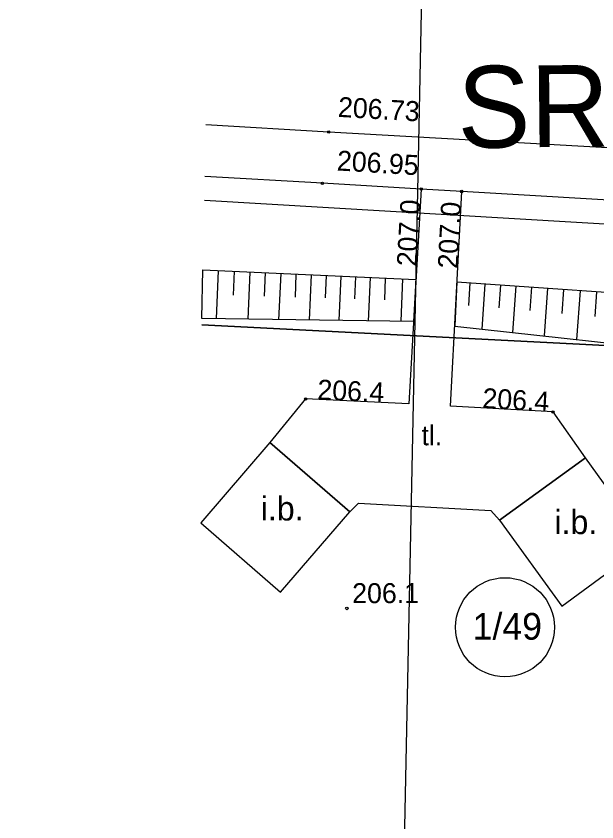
# Model space of a CAD drawing. Extents: x 6512606 to 6513006, y 6022524 to 6022728.
# Drawn here: x 6512694.69 to 6512716.48, y 6022610.86 to 6022641.08 of the extents above; entities that cross this region are included whole.
import ezdxf

# ---------------------------------------------------------------- set-up
doc = ezdxf.new("R2010")
doc.units = 0
for name, color, linetype in [('000 Inne (niezydentyfikowane)', 7, 'Continuous'), ('211-numer działki ewidencyjnej', 7, 'Continuous'), ('217-kontur klasyfikacyjny', 7, 'Continuous'), ('218-kontur użytku gruntowego', 7, 'Continuous'), ('4', 7, 'Continuous'), ('6', 7, 'Continuous'), ('chodnik (powierzchnia)', 7, 'Continuous'), ('Default', 7, 'Continuous'), ('inna budowla (powierzchnia)', 7, 'Continuous'), ('inna budowla (powierzchnia)-Atr17', 7, 'Continuous'), ('krawężnik (linia)', 7, 'Continuous'), ('maxp_inst_wodociągowa', 7, 'Continuous'), ('Obszar opracowania', 7, 'Continuous'), ('plac (powierzchnia)', 7, 'Continuous'), ('plac (powierzchnia)-Atr17', 7, 'Continuous'), ('przewód elektroenergetyczny (linia)', 7, 'Continuous'), ('punkt wysokościowy naturalny', 7, 'Continuous'), ('punkt wysokościowy naturalny-Atr2', 7, 'Continuous'), ('punkt wysokościowy sztuczny', 7, 'Continuous'), ('punkt wysokościowy sztuczny-Atr2', 7, 'Continuous'), ('skarpa nieumocniona (powierzchnia)', 7, 'Continuous')]:
    doc.layers.add(name, color=color, linetype=linetype)

# ---------------------------------------------------------------- blocks, each defined once
blk = doc.blocks.new('PW01')
at = {"layer": 'Default'}
blk.add_circle((0, 0), 0.45, dxfattribs=at)
blk = doc.blocks.new('PW02')
at = {"layer": 'Default'}
blk.add_circle((0, 0), 0.45, dxfattribs=at)

msp = doc.modelspace()

# ---------------------------------------------------------------- linework, layer by layer
at = {"layer": '000 Inne (niezydentyfikowane)'}
for p, q in [((6512702.27, 6022631.54), (6512702.19, 6022629.72)), ((6512702.87, 6022631.51), (6512702.83, 6022630.61)), ((6512703.46, 6022631.48), (6512703.38, 6022629.71)), ((6512704.04, 6022631.46), (6512704, 6022630.58)), ((6512704.62, 6022631.43), (6512704.54, 6022629.69)), ((6512705.19, 6022631.4), (6512705.16, 6022630.54)), ((6512705.76, 6022631.38), (6512705.68, 6022629.67)), ((6512706.32, 6022631.35), (6512706.28, 6022630.51)), ((6512706.88, 6022631.33), (6512706.8, 6022629.66)), ((6512707.43, 6022631.3), (6512707.39, 6022630.48)), ((6512707.98, 6022631.28), (6512707.9, 6022629.64)), ((6512708.54, 6022631.25), (6512708.51, 6022630.44)), ((6512709.19, 6022631.22), (6512709.12, 6022629.63))]:
    msp.add_line(p, q, dxfattribs=at)
for points in [[(6512711.72, 6022631.07), (6512711.66, 6022630.23)], [(6512712.28, 6022631.03), (6512712.17, 6022629.34)], [(6512712.86, 6022630.99), (6512712.8, 6022630.13)], [(6512713.44, 6022630.95), (6512713.32, 6022629.21)], [(6512714.03, 6022630.91), (6512713.97, 6022630.03)], [(6512714.63, 6022630.87), (6512714.5, 6022629.08)], [(6512715.23, 6022630.82), (6512715.17, 6022629.92)], [(6512715.85, 6022630.78), (6512715.72, 6022628.95)], [(6512716.47, 6022630.74), (6512716.41, 6022629.81)]]:
    msp.add_lwpolyline(points, dxfattribs=at)
at = {"layer": '217-kontur klasyfikacyjny'}
msp.add_lwpolyline([(6512729.5, 6022628.07), (6512701.66, 6022629.496)], dxfattribs=at)
at = {"layer": '218-kontur użytku gruntowego'}
for points in [[(6512701.66, 6022629.496), (6512729.5, 6022628.07)], [(6512729.5, 6022628.07), (6512701.66, 6022629.496)]]:
    msp.add_lwpolyline(points, dxfattribs=at)
at = {"layer": '6'}
msp.add_circle((6512713.034, 6022618.154), 1.859, dxfattribs=at)
at = {"layer": 'chodnik (powierzchnia)'}
for points in [[(6512709.89, 6022634.59), (6512706.18, 6022634.81), (6512701.774, 6022635.063)], [(6512726.27, 6022633.62), (6512711.41, 6022634.5)]]:
    msp.add_lwpolyline(points, dxfattribs=at)
at = {"layer": 'inna budowla (powierzchnia)'}
for points in [[(6512707.21, 6022622.49), (6512704.21, 6022625.09), (6512701.62, 6022622.07), (6512704.61, 6022619.47)], [(6512716.05, 6022624.51), (6512712.83, 6022622.17), (6512715.17, 6022618.95), (6512718.37, 6022621.3)]]:
    msp.add_lwpolyline(points, close=True, dxfattribs=at)
at = {"layer": 'krawężnik (linia)'}
msp.add_lwpolyline([(6512702.473, 6022669.202), (6512710.9, 6022668.72), (6512710.75, 6022664.74), (6512710.88, 6022663.85), (6512711.57, 6022663.54), (6512725.79, 6022662.66), (6512724.94, 6022645.24), (6512724.45, 6022635.71), (6512706.43, 6022636.73), (6512701.814, 6022636.999)], dxfattribs=at)
at = {"layer": 'Obszar opracowania'}
msp.add_lwpolyline([(6512710.98, 6022693.84), (6512748.35, 6022694.16), (6512798.11, 6022695.25), (6512807.47, 6022695.46), (6512809.66, 6022606.87), (6512863.71, 6022622.03), (6512875.13, 6022581.36), (6512755.22, 6022535.25), (6512691.61, 6022568.03), (6512709.16, 6022605.16)], close=True, dxfattribs=at)
at = {"layer": 'plac (powierzchnia)'}
msp.add_lwpolyline([(6512704.21, 6022625.09), (6512707.21, 6022622.49), (6512707.54, 6022622.81), (6512712.5, 6022622.54), (6512712.83, 6022622.17), (6512716.05, 6022624.51), (6512714.84, 6022626.23), (6512710.99, 6022626.45), (6512711.41, 6022634.5), (6512709.89, 6022634.59), (6512709.42, 6022626.54), (6512705.55, 6022626.72)], close=True, dxfattribs=at)
at = {"layer": 'przewód elektroenergetyczny (linia)'}
msp.add_lwpolyline([(6512701.756, 6022634.173), (6512720.37, 6022633.07), (6512728.65, 6022632.8), (6512729.84, 6022646.1), (6512731.03, 6022668.44), (6512718.53, 6022669.06), (6512712.43, 6022669.64), (6512702.495, 6022670.296)], dxfattribs=at)
at = {"layer": 'skarpa nieumocniona (powierzchnia)'}
for points in [[(6512709.69, 6022631.2), (6512709.6, 6022629.62), (6512701.66, 6022629.73), (6512701.7, 6022631.56)], [(6512709.69, 6022631.2), (6512709.6, 6022629.62), (6512701.66, 6022629.73), (6512701.7, 6022631.56)], [(6512711.15, 6022629.45), (6512720.5, 6022628.42), (6512728.41, 6022629.69), (6512727.72, 6022631.22), (6512720.25, 6022630.48), (6512711.23, 6022631.1)], [(6512711.15, 6022629.45), (6512720.5, 6022628.42), (6512728.41, 6022629.69), (6512727.72, 6022631.22), (6512720.25, 6022630.48), (6512711.23, 6022631.1)]]:
    msp.add_lwpolyline(points, close=True, dxfattribs=at)

# ---------------------------------------------------------------- block references
at = {"layer": 'punkt wysokościowy naturalny', "xscale": 0.1, "yscale": 0.10000000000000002}
for p in [(6512709.89, 6022634.59), (6512711.41, 6022634.5), (6512705.55, 6022626.72), (6512714.84, 6022626.23), (6512707.1, 6022618.86)]:
    msp.add_blockref('PW01', p, dxfattribs=at)
at = {"layer": 'punkt wysokościowy sztuczny', "xscale": 0.1, "yscale": 0.10000000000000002}
for p in [(6512706.42, 6022636.73), (6512706.18, 6022634.81)]:
    msp.add_blockref('PW02', p, dxfattribs=at)

# ---------------------------------------------------------------- texts
at = {"layer": '211-numer działki ewidencyjnej'}
msp.add_text('1/49', height=1, dxfattribs=at).set_placement((6512711.82, 6022617.69))
at = {"layer": '4'}
msp.add_text('1/49', height=1, dxfattribs=at).set_placement((6512711.82, 6022617.69))
at = {"layer": 'inna budowla (powierzchnia)-Atr17'}
for p in [(6512703.87, 6022622.16), (6512714.89, 6022621.65)]:
    msp.add_text('i.b.', height=0.9, dxfattribs=at).set_placement(p)
at = {"layer": 'maxp_inst_wodociągowa'}
msp.add_text('SR', height=3.0671, rotation=0.5777, dxfattribs=at).set_placement((6512711.262, 6022636.131))
at = {"layer": 'plac (powierzchnia)-Atr17'}
msp.add_text('tl.', height=0.75, dxfattribs=at).set_placement((6512709.9, 6022624.98))
at = {"layer": 'punkt wysokościowy naturalny-Atr2'}
for s, rotation, p in [('207.0', 86.658, (6512709.72, 6022631.67)), ('207.0', 87.013, (6512711.26, 6022631.59)), ('206.4', 357.337, (6512705.98, 6022626.7)), ('206.4', 356.729, (6512712.17, 6022626.38))]:
    msp.add_text(s, height=0.75, rotation=rotation, dxfattribs=at).set_placement(p)
msp.add_text('206.1', height=0.75, dxfattribs=at).set_placement((6512707.3, 6022619.06))
at = {"layer": 'punkt wysokościowy sztuczny-Atr2'}
for s, rotation, p in [('206.73', 356.76, (6512706.75, 6022637.3)), ('206.95', 356.61, (6512706.71, 6022635.29))]:
    msp.add_text(s, height=0.75, rotation=rotation, dxfattribs=at).set_placement(p)

doc.saveas('drawing.dxf')
